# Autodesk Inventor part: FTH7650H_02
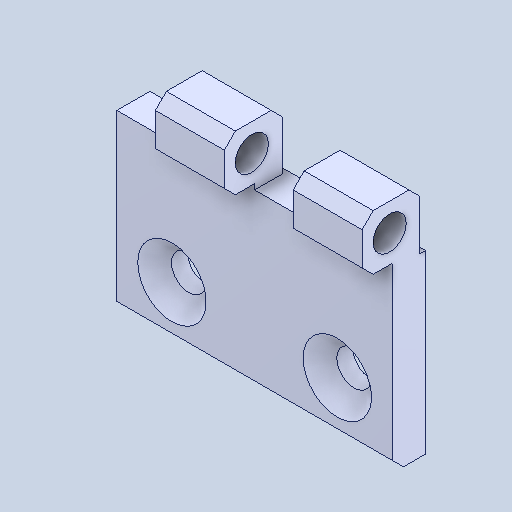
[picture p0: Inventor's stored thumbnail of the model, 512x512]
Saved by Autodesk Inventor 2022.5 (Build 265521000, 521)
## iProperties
Created: 2024-08
Part Number: FTH7650H_02
Material: 一般
Document SubType Name: Modeling
Designer: ImaoCorp
Density: 1 g/cm^3
Appearance: 既定
Author: ImaoCorp
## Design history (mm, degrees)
feature "FTH7650H_02"
node "ソリッド1"
